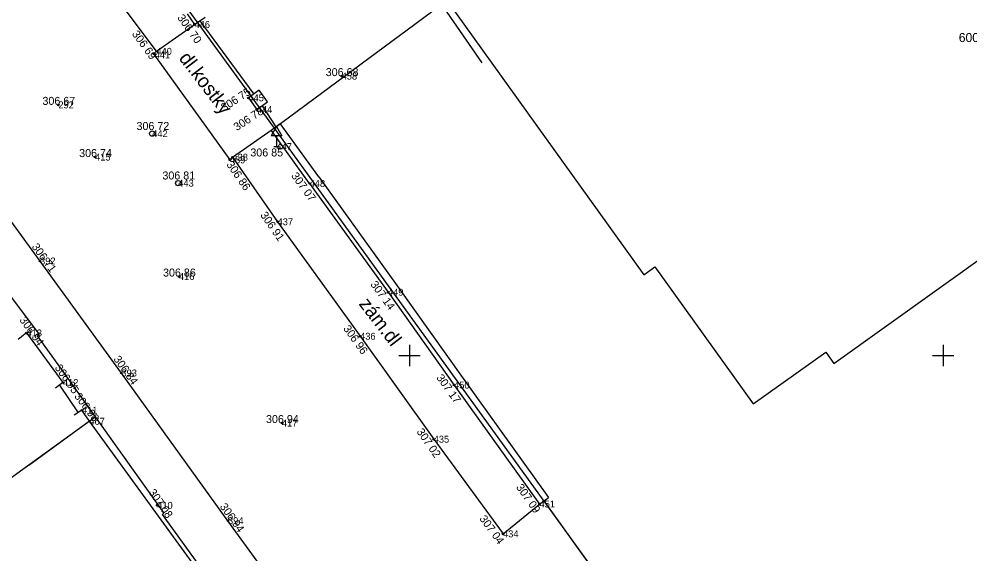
# Model space of a CAD drawing. Extents: x -492811 to -492366, y -1127107 to -1126748.
# Drawn here: x -492614.64 to -492578.99, y -1126947.44 to -1126927.39 of the extents above; entities that cross this region are included whole.
import ezdxf

# ---------------------------------------------------------------- set-up
doc = ezdxf.new("R2010")
doc.units = 0
for name, color, linetype in [('body', 7, 'Continuous'), ('doprava', 7, 'Continuous'), ('katastrální mapa', 7, 'Continuous'), ('oplocení', 7, 'Continuous'), ('podrobný výškový bod', 7, 'Continuous'), ('popis ploch', 7, 'Continuous'), ('rozhraní ploch', 7, 'Continuous'), ('stavební objekt', 7, 'Continuous'), ('síť', 7, 'Continuous'), ('vodovod', 7, 'Continuous'), ('vstup na pozemek', 7, 'Continuous'), ('výšky', 7, 'Continuous'), ('čísla bodů', 7, 'Continuous')]:
    doc.layers.add(name, color=color, linetype=linetype)

msp = doc.modelspace()

# ---------------------------------------------------------------- linework, layer by layer
at = {"layer": 'body'}
for p, q in [((-492608.062, -1126927.589), (-492608.062, -1126927.589)), ((-492609.491, -1126928.597), (-492609.491, -1126928.597)), ((-492609.594, -1126928.686), (-492609.594, -1126928.686)), ((-492602.547, -1126929.526), (-492602.547, -1126929.526)), ((-492606.042, -1126930.342), (-492606.042, -1126930.342)), ((-492613.166, -1126930.605), (-492613.166, -1126930.605)), ((-492605.73, -1126930.782), (-492605.73, -1126930.782)), ((-492609.648, -1126931.683), (-492609.648, -1126931.683)), ((-492604.99, -1126932.17), (-492604.99, -1126932.17)), ((-492611.791, -1126932.561), (-492611.791, -1126932.561)), ((-492606.639, -1126932.569), (-492606.639, -1126932.569)), ((-492606.738, -1126932.666), (-492606.738, -1126932.666)), ((-492608.672, -1126933.539), (-492608.672, -1126933.539)), ((-492603.746, -1126933.551), (-492603.746, -1126933.551)), ((-492604.947, -1126934.987), (-492604.947, -1126934.987)), ((-492613.852, -1126936.459), (-492613.852, -1126936.459)), ((-492608.646, -1126937.041), (-492608.646, -1126937.041)), ((-492600.808, -1126937.63), (-492600.808, -1126937.63)), ((-492614.36, -1126939.157), (-492614.36, -1126939.157)), ((-492601.854, -1126939.279), (-492601.854, -1126939.279)), ((-492610.802, -1126940.657), (-492610.802, -1126940.657)), ((-492612.995, -1126941.016), (-492612.995, -1126941.016)), ((-492598.331, -1126941.11), (-492598.331, -1126941.11)), ((-492612.281, -1126942.05), (-492612.281, -1126942.05)), ((-492612.005, -1126942.467), (-492612.005, -1126942.467)), ((-492604.785, -1126942.534), (-492604.785, -1126942.534)), ((-492599.096, -1126943.14), (-492599.096, -1126943.14)), ((-492609.46, -1126945.619), (-492609.46, -1126945.619)), ((-492595.128, -1126945.569), (-492595.128, -1126945.569)), ((-492606.807, -1126946.194), (-492606.807, -1126946.194)), ((-492596.496, -1126946.689), (-492596.496, -1126946.689))]:
    msp.add_line(p, q, dxfattribs=at)
at = {"layer": 'doprava'}
for p, q in [((-492604.99, -1126931.41), (-492605.19, -1126931.77)), ((-492604.99, -1126931.41), (-492604.79, -1126931.77)), ((-492604.79, -1126931.77), (-492605.19, -1126931.77)), ((-492604.99, -1126931.77), (-492604.99, -1126932.17)), ((-492605.09, -1126932.17), (-492604.89, -1126932.17))]:
    msp.add_line(p, q, dxfattribs=at)
at = {"layer": 'katastrální mapa'}
for p, q in [((-492605.08, -1126931.48), (-492598.6, -1126926.69)), ((-492598.6, -1126926.69), (-492591.22, -1126936.98)), ((-492608.27, -1126927.08), (-492605.08, -1126931.48)), ((-492584.09, -1126940.3), (-492567, -1126928.06)), ((-492605.08, -1126931.48), (-492577.77, -1126969.24)), ((-492616.43, -1126935.83), (-492613.89, -1126939.21)), ((-492591.22, -1126936.98), (-492590.8, -1126936.68)), ((-492590.8, -1126936.68), (-492587.12, -1126941.81)), ((-492613.96, -1126939.26), (-492613.89, -1126939.21)), ((-492613.96, -1126939.26), (-492613.12, -1126940.43)), ((-492587.12, -1126941.81), (-492584.4, -1126939.87)), ((-492584.4, -1126939.87), (-492584.09, -1126940.3)), ((-492613.12, -1126940.43), (-492611.79, -1126942.3)), ((-492619.54, -1126947.9), (-492611.79, -1126942.3)), ((-492611.79, -1126942.3), (-492609.21, -1126945.91)), ((-492609.28, -1126945.96), (-492609.21, -1126945.91)), ((-492609.28, -1126945.96), (-492605.92, -1126950.59))]:
    msp.add_line(p, q, dxfattribs=at)
at = {"layer": 'oplocení'}
for p, q in [((-492608.335, -1126927.188), (-492608.062, -1126927.589)), ((-492608.062, -1126927.589), (-492607.661, -1126927.316)), ((-492605.632, -1126930.056), (-492606.042, -1126930.342)), ((-492605.323, -1126930.494), (-492605.632, -1126930.056)), ((-492606.042, -1126930.342), (-492605.73, -1126930.782)), ((-492605.73, -1126930.782), (-492605.323, -1126930.494)), ((-492605.186, -1126931.552), (-492604.845, -1126931.307)), ((-492603.405, -1126933.306), (-492604.845, -1126931.307)), ((-492603.746, -1126933.551), (-492605.186, -1126931.552)), ((-492603.746, -1126933.551), (-492600.808, -1126937.63)), ((-492603.405, -1126933.306), (-492600.467, -1126937.385)), ((-492600.467, -1126937.385), (-492597.989, -1126940.866)), ((-492600.808, -1126937.63), (-492598.331, -1126941.11)), ((-492614.36, -1126939.157), (-492614.679, -1126939.395)), ((-492614.36, -1126939.157), (-492612.995, -1126941.016)), ((-492612.995, -1126941.016), (-492613.277, -1126941.223)), ((-492598.331, -1126941.11), (-492595.128, -1126945.569)), ((-492597.989, -1126940.866), (-492594.787, -1126945.324)), ((-492612.281, -1126942.05), (-492612.57, -1126942.241)), ((-492612.005, -1126942.467), (-492612.281, -1126942.05)), ((-492595.128, -1126945.569), (-492594.787, -1126945.324))]:
    msp.add_line(p, q, dxfattribs=at)
at = {"layer": 'podrobný výškový bod'}
for centre in [(-492608.062, -1126927.589), (-492609.594, -1126928.686), (-492602.547, -1126929.526), (-492606.042, -1126930.342), (-492613.166, -1126930.605), (-492605.73, -1126930.782), (-492611.791, -1126932.561), (-492606.639, -1126932.569), (-492606.738, -1126932.666), (-492603.746, -1126933.551), (-492604.947, -1126934.987), (-492613.852, -1126936.459), (-492608.646, -1126937.041), (-492600.808, -1126937.63), (-492614.36, -1126939.157), (-492601.854, -1126939.279), (-492610.802, -1126940.657), (-492612.995, -1126941.016), (-492598.331, -1126941.11), (-492612.281, -1126942.05), (-492604.785, -1126942.534), (-492599.096, -1126943.14), (-492609.46, -1126945.619), (-492595.128, -1126945.569), (-492606.807, -1126946.194), (-492596.496, -1126946.689)]:
    msp.add_circle(centre, 0.03, dxfattribs=at)
at = {"layer": 'rozhraní ploch'}
for p, q in [((-492609.491, -1126928.597), (-492611.316, -1126926.155)), ((-492609.491, -1126928.597), (-492608.062, -1126927.589)), ((-492609.594, -1126928.686), (-492609.491, -1126928.597)), ((-492609.594, -1126928.686), (-492606.738, -1126932.666)), ((-492606.639, -1126932.569), (-492605.186, -1126931.552)), ((-492606.738, -1126932.666), (-492606.639, -1126932.569)), ((-492606.639, -1126932.569), (-492604.947, -1126934.987)), ((-492613.852, -1126936.459), (-492615.628, -1126934.028)), ((-492604.947, -1126934.987), (-492601.854, -1126939.279)), ((-492610.802, -1126940.657), (-492613.852, -1126936.459)), ((-492601.854, -1126939.279), (-492599.096, -1126943.14)), ((-492606.807, -1126946.194), (-492610.802, -1126940.657)), ((-492599.096, -1126943.14), (-492596.496, -1126946.689)), ((-492596.496, -1126946.689), (-492595.128, -1126945.569)), ((-492603.749, -1126950.422), (-492606.807, -1126946.194))]:
    msp.add_line(p, q, dxfattribs=at)
at = {"layer": 'stavební objekt'}
for p, q in [((-492598.719, -1126926.967), (-492597.292, -1126929.029)), ((-492612.005, -1126942.467), (-492614.271, -1126944.119)), ((-492606.057, -1126950.624), (-492612.005, -1126942.467))]:
    msp.add_line(p, q, dxfattribs=at)
at = {"layer": 'síť'}
for p, q in [((-492600, -1126939.6), (-492600, -1126940.4)), ((-492580, -1126939.6), (-492580, -1126940.4)), ((-492600.4, -1126940), (-492599.6, -1126940)), ((-492580.4, -1126940), (-492579.6, -1126940))]:
    msp.add_line(p, q, dxfattribs=at)
at = {"layer": 'vodovod'}
for centre in [(-492609.648, -1126931.683), (-492608.672, -1126933.539)]:
    msp.add_circle(centre, 0.1, dxfattribs=at)
at = {"layer": 'vstup na pozemek'}
for p, q in [((-492607.862, -1126927.453), (-492605.837, -1126930.199)), ((-492605.527, -1126930.638), (-492605.015, -1126931.429)), ((-492613.124, -1126941.111), (-492612.428, -1126942.147)), ((-492592.748, -1126948.516), (-492594.957, -1126945.446))]:
    msp.add_line(p, q, dxfattribs=at)

# ---------------------------------------------------------------- texts
at = {"layer": 'katastrální mapa'}
msp.add_text('600', height=0.34, dxfattribs=at).set_placement((-492579.41, -1126928.25))
at = {"layer": 'popis ploch'}
for s, p in [('dl.kostky', (-492608.671, -1126928.862)), ('zám.dl', (-492601.922, -1126938.073))]:
    msp.add_text(s, height=0.52, rotation=307.4503, dxfattribs=at).set_placement(p)
at = {"layer": 'výšky'}
for s, rotation, p in [('306 70 ', 305.2741, (-492608.722, -1126927.336)), ('306 69 ', 306.1305, (-492610.425, -1126927.947)), ('306 75 ', 33.1363, (-492606.946, -1126930.86)), ('306 78 ', 33.4614, (-492606.473, -1126931.593)), ('306 86 ', 304.543, (-492606.881, -1126932.839)), ('307 07 ', 306.172, (-492604.455, -1126933.267)), ('306 91 ', 304.6096, (-492605.612, -1126934.735)), ('306 71 ', 306.0086, (-492614.182, -1126935.924)), ('307 14 ', 305.949, (-492601.484, -1126937.334)), ('306 94 ', 305.5714, (-492614.64, -1126938.673)), ('306 96 ', 305.6956, (-492602.502, -1126938.992)), ('306 84 ', 305.7626, (-492611.116, -1126940.138)), ('306 95 ', 304.9923, (-492613.316, -1126940.461)), ('307 17 ', 305.7818, (-492599.011, -1126940.834)), ('306 98 ', 306.6822, (-492612.586, -1126941.533)), ('307 02 ', 304.8376, (-492599.752, -1126942.858)), ('307 08 ', 304.8261, (-492609.8, -1126945.13)), ('307 09 ', 305.1424, (-492596.02, -1126944.942)), ('306 94 ', 305.6256, (-492607.129, -1126945.667)), ('307 04 ', 306.2175, (-492597.397, -1126946.12))]:
    msp.add_text(s, height=0.3, rotation=rotation, dxfattribs=at).set_placement(p)
for s, p in [('306 68 ', (-492603.143, -1126929.526)), ('306 67 ', (-492613.762, -1126930.605)), ('306 72 ', (-492610.236, -1126931.546)), ('306 74 ', (-492612.387, -1126932.561)), ('306 85 ', (-492605.969, -1126932.538)), ('306 81 ', (-492609.265, -1126933.402)), ('306 86 ', (-492609.242, -1126937.041)), ('306 94 ', (-492605.381, -1126942.534))]:
    msp.add_text(s, height=0.3, dxfattribs=at).set_placement(p)
at = {"layer": 'čísla bodů'}
for s, p in [('446', (-492608.062, -1126927.719)), ('441', (-492609.553, -1126928.857)), ('440', (-492609.491, -1126928.727)), ('458', (-492602.547, -1126929.656)), ('445', (-492606.042, -1126930.472)), ('292', (-492613.166, -1126930.735)), ('444', (-492605.73, -1126930.912)), ('442', (-492609.648, -1126931.813)), ('447', (-492604.99, -1126932.3)), ('415', (-492611.791, -1126932.691)), ('439', (-492606.738, -1126932.796)), ('438', (-492606.639, -1126932.699)), ('443', (-492608.672, -1126933.669)), ('448', (-492603.746, -1126933.681)), ('437', (-492604.947, -1126935.117)), ('392', (-492613.852, -1126936.589)), ('416', (-492608.646, -1126937.171)), ('449', (-492600.808, -1126937.76)), ('413', (-492614.36, -1126939.287)), ('436', (-492601.854, -1126939.409)), ('393', (-492610.802, -1126940.787)), ('412', (-492612.995, -1126941.146)), ('450', (-492598.331, -1126941.24)), ('411', (-492612.281, -1126942.18)), ('467', (-492612.005, -1126942.597)), ('417', (-492604.785, -1126942.664)), ('435', (-492599.096, -1126943.27)), ('410', (-492609.46, -1126945.749)), ('451', (-492595.128, -1126945.699)), ('394', (-492606.807, -1126946.324)), ('434', (-492596.496, -1126946.819))]:
    msp.add_text(s, height=0.26, dxfattribs=at).set_placement(p)

doc.saveas('drawing.dxf')
